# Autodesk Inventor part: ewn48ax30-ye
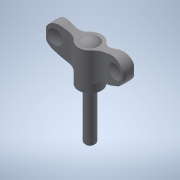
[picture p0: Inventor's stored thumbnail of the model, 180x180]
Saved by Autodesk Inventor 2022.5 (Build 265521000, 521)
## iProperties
Created: 2016-12
Part Number: ewn48ax30-ye
Material: 一般
Document SubType Name: Modeling
Designer: imaocorp
Density: 1 g/cm^3
Appearance: 既定
Author: imaocorp
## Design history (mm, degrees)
node "ewn48ax30-ye.x_t1"
node "ewn48ax30-ye"
node "Base1"
